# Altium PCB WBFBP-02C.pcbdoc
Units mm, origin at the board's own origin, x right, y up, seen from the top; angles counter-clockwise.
Board outline 14.09 x 13.41 mm, 2 copper layers (Top Layer, Bottom Layer), stack 0 mm thick; 1 components, 0 nets, 2 pads, 0 vias.
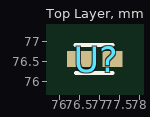
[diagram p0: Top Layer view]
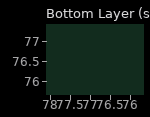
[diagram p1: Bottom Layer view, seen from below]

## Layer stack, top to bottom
Top Layer: signal copper (thickness not stored)
Bottom Layer: signal copper (thickness not stored)

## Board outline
83.94,69.85 69.85,69.85 69.85,83.26 83.94,83.26

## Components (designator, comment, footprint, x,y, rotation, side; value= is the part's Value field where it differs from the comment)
U? "" WBFBP-02C 76.925,76.56 r0 top

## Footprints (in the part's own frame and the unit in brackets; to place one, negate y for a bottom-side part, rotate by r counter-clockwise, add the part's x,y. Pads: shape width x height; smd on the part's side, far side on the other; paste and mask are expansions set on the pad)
WBFBP-02C [mm]
  rect 0.62x0.4 smd: 1(-0.415,0)
  rect 0.5x0.4 smd: 2(0.415,0)
  silkscreen extent -0.52,-0.35 0.41,0.35

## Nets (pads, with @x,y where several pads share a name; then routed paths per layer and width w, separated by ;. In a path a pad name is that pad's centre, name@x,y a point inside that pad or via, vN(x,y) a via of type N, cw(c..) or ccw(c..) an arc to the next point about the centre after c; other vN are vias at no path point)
pads on no net: U?.1 U?.2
